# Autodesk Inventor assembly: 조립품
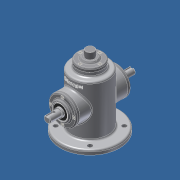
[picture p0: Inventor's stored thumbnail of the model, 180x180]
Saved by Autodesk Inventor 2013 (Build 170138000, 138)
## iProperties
Created: 2014-12
Part Number: 조립품
Document SubType Name: Assembly
Designer: CAD-B31
Author: CAD-B31
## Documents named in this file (12)
- C:\Users\CAD-B31\Desktop\441228V1005\조립품.iam
- C:\Users\CAD-B31\Desktop\441228V1005\본체.ipt
- C:\Users\CAD-B31\Desktop\441228V1005\편심축.ipt
- C:\Users\CAD-B31\Desktop\441228V1005\커버.ipt
- C:\Users\CAD-B31\Desktop\441228V1005\상단커버.ipt
- C:\Users\CAD-B31\Desktop\441228V1005\슬라이드.ipt
- C:\Users\CAD-B31\Desktop\441228V1005\베어링 6002.ipt
- 베어링 6002.ipt
- C:\Users\CAD-B31\Desktop\441228V1005\오일실.ipt
- 오일실.ipt
- C:\Users\CAD-B31\Desktop\441228V1005\M3x0.5x8.ipt
- M3x0.5.ipt
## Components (12 placed, 1 different names)
1. M3x0.5:2 — 각도:2
2. M3x0.5:4
3. M3x0.5:5
4. M3x0.5:6
5. M3x0.5:3 — 각도:1
6. M3x0.5:7
7. M3x0.5:8
8. M3x0.5:9
9. M3x0.5:1 — 각도:3
10. M3x0.5:10
11. M3x0.5:11
12. M3x0.5:12
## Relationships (3: Angle 3)
- 각도:1 [Angle]: M3x0.5:3
- 각도:2 [Angle]: M3x0.5:2
- 각도:3 [Angle]: M3x0.5:1
